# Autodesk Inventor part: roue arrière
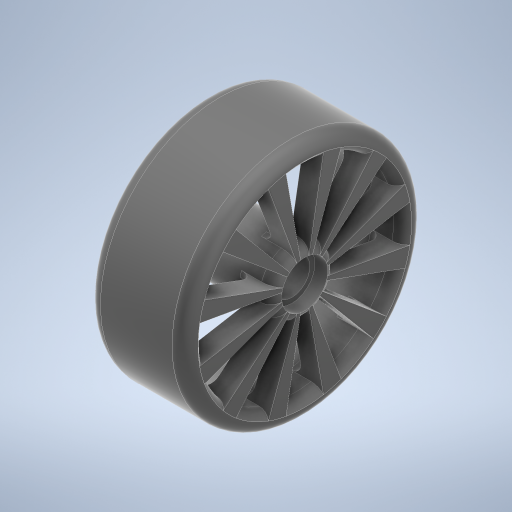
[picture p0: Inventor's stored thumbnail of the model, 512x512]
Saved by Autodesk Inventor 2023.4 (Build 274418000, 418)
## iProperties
Created: 2023-11
Part Number: roue arrière
Material: Plastique ABS
Document SubType Name: Modeling
Designer: mel
Density: 1.06 g/cm^3
Appearance: Lisse - Noir
Author: mel
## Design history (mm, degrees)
sketch "Esquisse1"
  geometry: L1 (0, 0)-(13, 0); L2 (14.988, -3.55)-(14.988, -16.393); L3 (12.988, -18.393)-(2, -18.393); L4 (0, -5)-(9.988, -5); L5 (11.988, -7)-(11.988, -13.393); L6 (9.988, -15.393)-(0, -15.393); L7 (0, 0)-(13, 0); L8 (0, -16.393)-(0, -15.393); L9 (0, -5)-(0, -3.55); L10 (13, 0)-(12, 0); L11 (0, 0)-(2, 0); L12 (2, -2.775)-(2, -3.55); L13 (2, -3.55)-(0, -3.55); L14 (2, -2.775)-(13, -2.775); L15 (13, -3.55)-(15, -3.55); L16 (13, -2.775)-(13, -3.55); A1 r 2 centre (2, -16.393) between (0, -16.393) and (2, -18.393); A2 r 2 centre (12.988, -16.393) between (12.988, -18.393) and (14.988, -16.393); A3 r 2 centre (9.988, -7) between (11.988, -7) and (9.988, -5); A4 r 2 centre (9.988, -13.393) between (9.988, -15.393) and (11.988, -13.393); 2 further points
  constraints: 32 end point, 9 tangent, 8 point on circle, 7 horizontal, 5 parallel, 4 centre point, 4 point on line, 3 perpendicular, 2 equal radius
  dimensions: "d0" = 15 distance of point (14.988, -18.393) point (-0.012, -18.393); "d2" = 2 radius of A1 (derived); "d3" = 3 distance between parallel lines of L6 L3; "d4" = 3 distance between parallel lines of L2 L5 (= d3); "d5" = 5 distance between parallel lines of L1 L4 (= d3 + d6); "d8" = 2 radius of A3 (derived); "d20" = 2 distance of L9.end L12.end; "d21" = 3.55 distance of L11.end L12.end
revolve "Révolution1" sketch "Esquisse1" stored, may be unused: angle "d9" = 90 deg
sketch "Esquisse2"
  geometry: L1 (0, 15.393)-(0, 5); L2 (-0.896, 4.919)-(-2.701, 15.154); L3 (0.896, 4.919)-(2.701, 15.154); C1 r 15.393 at (0, 0) reference; C2 r 5 at (0, 0) reference; A1 r 15.393 centre (0, 0) between (0, 15.393) and (-2.701, 15.154) reference; A2 r 5 centre (0, 0) between (0, 5) and (-0.896, 4.919) reference; 5 further points
  constraints: 6 end point, 4 point on circle, 2 symmetric about line, 1 vertical
  dimensions: "d10" = 10 deg angle of L1 L2
extrude "Extrusion1" cut sketch "Esquisse2" extent not by distance; stored distance "d11" = 0; taper "d12" = 0 deg
pattern_circular "Réseau circulaire1" dims angle "d14" = 360 deg
fillet "Congé1" dims "d16" = 2
fillet "Congé2" dims "d17" = 2
fillet "Congé3" dims "d18" = 2
feature "Ĕ耀Ė耀Ę耀Ě耀Ĝ耀Ğ耀Ġ耀Ģ耀" dims "d0" = 15, "d2" = 2 (derived), "d3" = 3, "d4" = 3 (= d3), "d5" = 5 (= d3 + d6), "d6" = 2, "d8" = 2 (derived), "d9" = 90 deg, "d10" = 10 deg, "d11" = 0, "d12" = 0, "d13" = 120, "d14" = 360 deg, "d16" = 2, "d17" = 2, "d18" = 2, "d20" = 2, "d21" = 3.55
feature "Ł耀Ń耀Ņ耀Ň耀ŉ耀ŋ耀ō耀ŏ耀" dims "d0" = 15, "d2" = 2 (derived), "d3" = 3, "d4" = 3 (= d3), "d5" = 5 (= d3 + d6), "d6" = 2, "d8" = 2 (derived), "d9" = 90 deg, "d10" = 10 deg, "d11" = 0, "d12" = 0, "d13" = 120, "d14" = 360 deg, "d16" = 2, "d17" = 2, "d18" = 2, "d20" = 2, "d21" = 3.55
node "Solide1"
